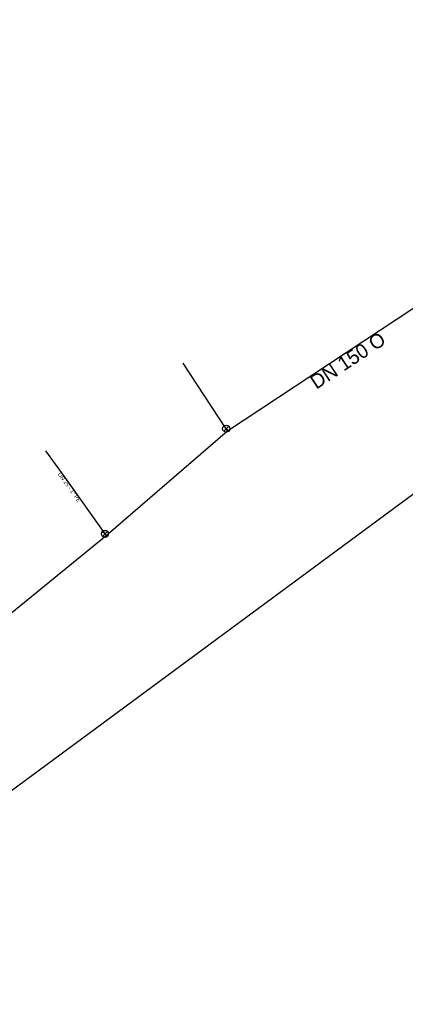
# Model space of a CAD drawing. Extents: x -451555 to -451079, y -1102113 to -1101586.
# Drawn here: x -451443.8 to -451400.3, y -1101778.3 to -1101668.7 of the extents above; entities that cross this region are included whole.
import ezdxf

# ---------------------------------------------------------------- set-up
doc = ezdxf.new("R2010")
doc.units = 0
for name, color, linetype in [('_pripojka_prevzato_z_dokumentace_', 7, 'Continuous'), ('_voda_smvak_prevzato_z_dokumentace_', 7, 'Continuous'), ('Default', 7, 'Continuous'), ('MoLevel 46', 7, 'Continuous'), ('MoLevel 53', 7, 'Continuous'), ('MoLevel 55', 7, 'Continuous')]:
    doc.layers.add(name, color=color, linetype=linetype)

# ---------------------------------------------------------------- blocks, each defined once
blk = doc.blocks.new('_uzaver_pripojka_')
at = {"layer": 'Default'}
for p, q in [((-0.000035, -0.000035), (0.000035, 0.000035)), ((0.000035, -0.000035), (-0.000035, 0.000035))]:
    blk.add_line(p, q, dxfattribs=at)
for radius in [0.00005, 0.0000025]:
    blk.add_circle((0, 0), radius, dxfattribs=at)

msp = doc.modelspace()

# ---------------------------------------------------------------- linework, layer by layer
at = {"layer": '_pripojka_prevzato_z_dokumentace_'}
for p, q in [((-451423.8, -1101709.68), (-451425.35, -1101707.33)), ((-451438.63, -1101720.2), (-451440.78, -1101717.18))]:
    msp.add_line(p, q, dxfattribs=at)
for points in [[(-451420.33, -1101714.98), (-451420.49, -1101714.7), (-451423.8, -1101709.68)], [(-451434, -1101726.73), (-451434.13, -1101726.53), (-451438.63, -1101720.2)]]:
    msp.add_lwpolyline(points, dxfattribs=at)
at = {"layer": '_voda_smvak_prevzato_z_dokumentace_'}
msp.add_line((-451391.04, -1101715.88), (-451475.73, -1101778.32), dxfattribs=at)
msp.add_lwpolyline([(-451352.37, -1101668.69), (-451374.89, -1101685.01), (-451391.64, -1101696.06), (-451420.33, -1101714.98), (-451434, -1101726.73), (-451445.03, -1101735.74), (-451449.89, -1101750.62)], dxfattribs=at)

# ---------------------------------------------------------------- block references
at = {"layer": 'MoLevel 53', "xscale": 7999.999999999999, "yscale": 7999.999999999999}
for p in [(-451420.49, -1101714.7), (-451434.13, -1101726.53)]:
    msp.add_blockref('_uzaver_pripojka_', p, dxfattribs=at)

# ---------------------------------------------------------------- texts
at = {"layer": 'MoLevel 46'}
msp.add_text('DN 150 O', height=1.605, rotation=33.408, dxfattribs=at).set_placement((-451410.35, -1101710.32))
at = {"layer": 'MoLevel 55'}
msp.add_text("DN 25 - 1'' PE", height=0.455, rotation=305.4216, dxfattribs=at).set_placement((-451439.46, -1101719.82))

doc.saveas('drawing.dxf')
